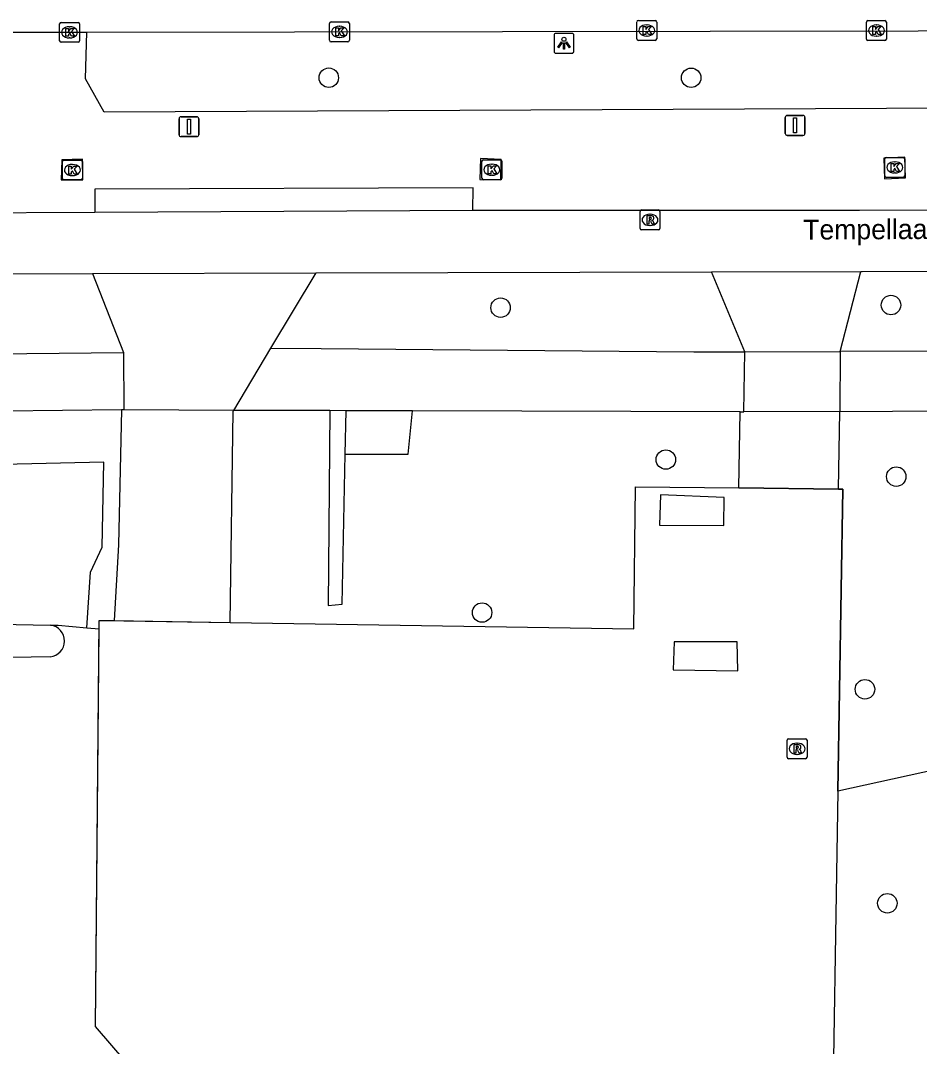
# Model space of a CAD drawing. Extents: x 160732 to 162105, y 387428 to 388479.
# Drawn here: x 160824.1 to 160869.3, y 388288.5 to 388340 of the extents above; entities that cross this region are included whole.
import ezdxf

# ---------------------------------------------------------------- set-up
doc = ezdxf.new("R2010")
doc.units = 0
for name, color, linetype in [('IMGEO_Berm_groen', 7, 'Continuous'), ('IMGEO_Boom', 7, 'Continuous'), ('IMGEO_Erf', 7, 'Continuous'), ('IMGEO_Fietspad_open', 7, 'Continuous'), ('IMGEO_Groenvoorziening', 7, 'Continuous'), ('IMGEO_Haag', 7, 'Continuous'), ('IMGEO_Hek', 7, 'Continuous'), ('IMGEO_Kolk', 7, 'Continuous'), ('IMGEO_Lichtpunt', 7, 'Continuous'), ('IMGEO_Openbare_ruimte_label', 7, 'Continuous'), ('IMGEO_Rijbaan_regionaal_gesloten', 7, 'Continuous'), ('IMGEO_Rioolput', 7, 'Continuous'), ('IMGEO_Verkeersbordpaal', 7, 'Continuous'), ('IMGEO_Voetpad_open', 7, 'Continuous'), ('IMGEO_Waterloop', 7, 'Continuous')]:
    doc.layers.add(name, color=color, linetype=linetype)

msp = doc.modelspace()

# ---------------------------------------------------------------- linework, layer by layer
at = {"layer": 'IMGEO_Berm_groen'}
msp.add_lwpolyline([(160958.33, 388337.953), (160955.414, 388335.943), (160949.557, 388333.455), (160946.326, 388335.988), (160828.33, 388335.445), (160827.393, 388337.122), (160827.446, 388339.467)], dxfattribs=at)
at = {"layer": 'IMGEO_Boom'}
for centre in [(160839.616, 388337.172), (160857.832, 388337.169), (160848.252, 388325.616), (160867.878, 388325.748), (160856.559, 388317.983), (160868.142, 388317.126), (160847.322, 388310.294), (160866.569, 388306.438), (160867.695, 388295.684)]:
    msp.add_circle(centre, 0.489, dxfattribs=at)
at = {"layer": 'IMGEO_Erf'}
for points in [[(160859.494, 388316.08), (160856.289, 388316.209), (160856.249, 388314.688), (160859.467, 388314.668), (160859.494, 388316.08)], [(160860.143, 388308.828), (160856.98, 388308.831), (160856.933, 388307.416), (160860.179, 388307.37), (160860.143, 388308.828)]]:
    msp.add_lwpolyline(points, dxfattribs=at)
at = {"layer": 'IMGEO_Fietspad_open'}
for points in [[(160846.854, 388330.5), (160846.875, 388331.641), (160827.861, 388331.568), (160827.854, 388330.405)], [(160846.854, 388330.5), (160827.854, 388330.405)], [(160948.514, 388330.666), (160948.148, 388330.665), (160866.301, 388330.493), (160846.854, 388330.5)], [(160827.854, 388330.405), (160814.057, 388330.327)], [(160755.948, 388328.392), (160760.439, 388328.038), (160771.107, 388327.578), (160775.664, 388327.463), (160782.867, 388327.387), (160794.417, 388327.291), (160806.927, 388327.23), (160817.787, 388327.309), (160827.738, 388327.334)], [(160827.738, 388327.334), (160838.976, 388327.375)], [(160838.976, 388327.375), (160858.861, 388327.415)], [(160858.861, 388327.415), (160866.359, 388327.435)], [(160866.359, 388327.435), (160866.422, 388327.435), (160948.07, 388327.597), (160952.894, 388327.601)]]:
    msp.add_lwpolyline(points, dxfattribs=at)
at = {"layer": 'IMGEO_Groenvoorziening'}
for points in [[(160839.672, 388320.441), (160839.58, 388310.643), (160840.283, 388310.715), (160840.437, 388318.25)], [(160840.437, 388318.25), (160840.482, 388320.438)], [(160840.437, 388318.25), (160843.608, 388318.256), (160843.817, 388320.428)], [(160834.65, 388309.796), (160854.955, 388309.47), (160855.041, 388316.62), (160860.223, 388316.558)], [(160865.213, 388301.314), (160865.461, 388316.495), (160865.235, 388316.498)], [(160825.631, 388309.669), (160826.011, 388309.655), (160827.456, 388309.525)], [(160865.213, 388301.314), (160864.893, 388281.692), (160834.148, 388282.21), (160827.887, 388289.487), (160828.067, 388309.47)], [(160871.548, 388302.717), (160865.213, 388301.314)]]:
    msp.add_lwpolyline(points, dxfattribs=at)
at = {"layer": 'IMGEO_Haag'}
for points in [[(160827.456, 388309.525), (160827.639, 388312.329), (160828.227, 388313.573), (160828.312, 388317.851), (160823.228, 388317.733)], [(160828.067, 388309.47), (160828.071, 388309.901), (160828.222, 388309.899), (160828.821, 388309.889)], [(160827.456, 388309.525), (160828.067, 388309.47)]]:
    msp.add_lwpolyline(points, dxfattribs=at)
at = {"layer": 'IMGEO_Hek'}
for points in [[(160834.65, 388309.796), (160854.955, 388309.47), (160855.041, 388316.62), (160860.223, 388316.558)], [(160860.223, 388316.558), (160865.235, 388316.498)], [(160865.235, 388316.498), (160865.461, 388316.495), (160865.213, 388301.314)], [(160865.213, 388301.314), (160864.893, 388281.692), (160834.148, 388282.21), (160827.887, 388289.487), (160828.071, 388309.901)], [(160828.071, 388309.901), (160828.235, 388309.896)], [(160828.235, 388309.896), (160834.65, 388309.796)]]:
    msp.add_lwpolyline(points, dxfattribs=at)
at = {"layer": 'IMGEO_Kolk'}
for p, q in [((160826.082, 388339.026), (160826.082, 388339.878)), ((160826.157, 388339.952), (160827.009, 388339.952)), ((160826.57, 388339.732), (160826.595, 388339.732)), ((160827.083, 388339.878), (160827.083, 388339.026)), ((160839.652, 388339.051), (160839.652, 388339.903)), ((160839.727, 388339.977), (160840.579, 388339.977)), ((160840.14, 388339.757), (160840.165, 388339.757)), ((160840.653, 388339.903), (160840.653, 388339.051)), ((160855.102, 388339.12), (160855.102, 388339.972)), ((160855.177, 388340.046), (160856.029, 388340.046)), ((160855.59, 388339.826), (160855.615, 388339.826)), ((160856.103, 388339.972), (160856.103, 388339.12)), ((160866.647, 388339.116), (160866.647, 388339.968)), ((160866.722, 388340.042), (160867.574, 388340.042)), ((160867.135, 388339.822), (160867.16, 388339.822)), ((160867.648, 388339.968), (160867.648, 388339.116)), ((160840.163, 388339.197), (160840.138, 388339.197)), ((160855.613, 388339.266), (160855.588, 388339.266)), ((160867.158, 388339.262), (160867.133, 388339.262)), ((160827.009, 388338.952), (160826.157, 388338.952)), ((160826.593, 388339.172), (160826.568, 388339.172)), ((160840.579, 388338.977), (160839.727, 388338.977)), ((160856.029, 388339.046), (160855.177, 388339.046)), ((160867.574, 388339.042), (160866.722, 388339.042)), ((160826.3, 388333.033), (160827.152, 388333.033)), ((160847.389, 388333.048), (160848.241, 388333.048)), ((160867.569, 388332.239), (160867.569, 388333.091)), ((160867.644, 388333.165), (160868.496, 388333.165)), ((160868.57, 388333.091), (160868.57, 388332.239)), ((160826.225, 388332.107), (160826.225, 388332.959)), ((160826.713, 388332.813), (160826.738, 388332.813)), ((160827.226, 388332.959), (160827.226, 388332.107)), ((160847.314, 388332.122), (160847.314, 388332.974)), ((160847.802, 388332.828), (160847.827, 388332.828)), ((160848.315, 388332.974), (160848.315, 388332.122)), ((160868.057, 388332.945), (160868.082, 388332.945)), ((160827.152, 388332.033), (160826.3, 388332.033)), ((160826.736, 388332.253), (160826.711, 388332.253)), ((160848.241, 388332.048), (160847.389, 388332.048)), ((160847.825, 388332.268), (160847.8, 388332.268)), ((160868.496, 388332.165), (160867.644, 388332.165)), ((160868.08, 388332.385), (160868.055, 388332.385))]:
    msp.add_line(p, q, dxfattribs=at)
for points in [[(160826.082, 388339.026), (160826.082, 388339.878)], [(160826.157, 388339.952), (160827.009, 388339.952)], [(160827.083, 388339.878), (160827.083, 388339.026)], [(160839.652, 388339.051), (160839.652, 388339.903)], [(160839.727, 388339.977), (160840.579, 388339.977)], [(160840.653, 388339.903), (160840.653, 388339.051)], [(160855.102, 388339.12), (160855.102, 388339.972)], [(160855.177, 388340.046), (160856.029, 388340.046)], [(160855.423, 388339.746), (160855.546, 388339.746), (160855.546, 388339.595), (160855.676, 388339.746), (160855.84, 388339.746), (160855.694, 388339.595), (160855.847, 388339.346), (160855.695, 388339.346), (160855.61, 388339.51), (160855.546, 388339.443), (160855.546, 388339.346), (160855.423, 388339.346), (160855.423, 388339.746)], [(160856.103, 388339.972), (160856.103, 388339.12)], [(160866.647, 388339.116), (160866.647, 388339.968)], [(160866.722, 388340.042), (160867.574, 388340.042)], [(160866.968, 388339.742), (160867.091, 388339.742), (160867.091, 388339.591), (160867.221, 388339.742), (160867.385, 388339.742), (160867.239, 388339.591), (160867.392, 388339.342), (160867.24, 388339.342), (160867.155, 388339.506), (160867.091, 388339.439), (160867.091, 388339.342), (160866.968, 388339.342), (160866.968, 388339.742)], [(160867.648, 388339.968), (160867.648, 388339.116)], [(160826.403, 388339.652), (160826.526, 388339.652), (160826.526, 388339.501), (160826.656, 388339.652), (160826.82, 388339.652), (160826.674, 388339.501), (160826.827, 388339.252), (160826.675, 388339.252), (160826.59, 388339.416), (160826.526, 388339.349), (160826.526, 388339.252), (160826.403, 388339.252), (160826.403, 388339.652)], [(160839.973, 388339.677), (160840.096, 388339.677), (160840.096, 388339.526), (160840.226, 388339.677), (160840.39, 388339.677), (160840.244, 388339.526), (160840.397, 388339.277), (160840.245, 388339.277), (160840.16, 388339.441), (160840.096, 388339.374), (160840.096, 388339.277), (160839.973, 388339.277), (160839.973, 388339.677)], [(160827.009, 388338.952), (160826.157, 388338.952)], [(160840.579, 388338.977), (160839.727, 388338.977)], [(160856.029, 388339.046), (160855.177, 388339.046)], [(160867.574, 388339.042), (160866.722, 388339.042)], [(160826.3, 388333.033), (160827.152, 388333.033)], [(160847.389, 388333.048), (160848.241, 388333.048)], [(160867.569, 388332.239), (160867.569, 388333.091)], [(160867.644, 388333.165), (160868.496, 388333.165)], [(160868.57, 388333.091), (160868.57, 388332.239)], [(160826.225, 388332.107), (160826.225, 388332.959)], [(160826.546, 388332.733), (160826.669, 388332.733), (160826.669, 388332.582), (160826.799, 388332.733), (160826.963, 388332.733), (160826.817, 388332.582), (160826.97, 388332.333), (160826.818, 388332.333), (160826.733, 388332.497), (160826.669, 388332.43), (160826.669, 388332.333), (160826.546, 388332.333), (160826.546, 388332.733)], [(160827.226, 388332.959), (160827.226, 388332.107)], [(160847.314, 388332.122), (160847.314, 388332.974)], [(160847.635, 388332.748), (160847.758, 388332.748), (160847.758, 388332.597), (160847.888, 388332.748), (160848.052, 388332.748), (160847.906, 388332.597), (160848.059, 388332.348), (160847.907, 388332.348), (160847.822, 388332.512), (160847.758, 388332.445), (160847.758, 388332.348), (160847.635, 388332.348), (160847.635, 388332.748)], [(160848.315, 388332.974), (160848.315, 388332.122)], [(160867.89, 388332.865), (160868.013, 388332.865), (160868.013, 388332.714), (160868.143, 388332.865), (160868.307, 388332.865), (160868.161, 388332.714), (160868.314, 388332.465), (160868.162, 388332.465), (160868.077, 388332.629), (160868.013, 388332.562), (160868.013, 388332.465), (160867.89, 388332.465), (160867.89, 388332.865)], [(160827.152, 388332.033), (160826.3, 388332.033)], [(160848.241, 388332.048), (160847.389, 388332.048)], [(160868.496, 388332.165), (160867.644, 388332.165)]]:
    msp.add_lwpolyline(points, dxfattribs=at)
for centre, start, end in [((160826.159, 388339.876), 91.552, 178.448), ((160826.159, 388339.876), 91.552, 178.448), ((160827.007, 388339.876), 1.552, 88.448), ((160827.007, 388339.876), 1.552, 88.448), ((160839.729, 388339.901), 91.552, 178.448), ((160839.729, 388339.901), 91.552, 178.448), ((160840.577, 388339.901), 1.552, 88.448), ((160840.577, 388339.901), 1.552, 88.448), ((160855.179, 388339.97), 91.552, 178.448), ((160855.179, 388339.97), 91.552, 178.448), ((160856.027, 388339.97), 1.552, 88.448), ((160856.027, 388339.97), 1.552, 88.448), ((160866.724, 388339.966), 91.552, 178.448), ((160866.724, 388339.966), 91.552, 178.448), ((160867.572, 388339.966), 1.552, 88.448), ((160867.572, 388339.966), 1.552, 88.448), ((160826.159, 388339.028), 181.552, 268.448), ((160826.159, 388339.028), 181.552, 268.448), ((160827.007, 388339.028), 271.552, 358.448), ((160827.007, 388339.028), 271.552, 358.448), ((160839.729, 388339.053), 181.552, 268.448), ((160839.729, 388339.053), 181.552, 268.448), ((160840.577, 388339.053), 271.552, 358.448), ((160840.577, 388339.053), 271.552, 358.448), ((160855.179, 388339.122), 181.552, 268.448), ((160855.179, 388339.122), 181.552, 268.448), ((160856.027, 388339.122), 271.552, 358.448), ((160856.027, 388339.122), 271.552, 358.448), ((160866.724, 388339.118), 181.552, 268.448), ((160866.724, 388339.118), 181.552, 268.448), ((160867.572, 388339.118), 271.552, 358.448), ((160867.572, 388339.118), 271.552, 358.448), ((160826.302, 388332.957), 91.552, 178.448), ((160826.302, 388332.957), 91.552, 178.448), ((160827.15, 388332.957), 1.552, 88.448), ((160827.15, 388332.957), 1.552, 88.448), ((160847.391, 388332.972), 91.552, 178.448), ((160847.391, 388332.972), 91.552, 178.448), ((160848.239, 388332.972), 1.552, 88.448), ((160848.239, 388332.972), 1.552, 88.448), ((160867.646, 388333.089), 91.552, 178.448), ((160867.646, 388333.089), 91.552, 178.448), ((160868.494, 388333.089), 1.552, 88.448), ((160868.494, 388333.089), 1.552, 88.448), ((160826.302, 388332.109), 181.552, 268.448), ((160826.302, 388332.109), 181.552, 268.448), ((160827.15, 388332.109), 271.552, 358.448), ((160827.15, 388332.109), 271.552, 358.448), ((160847.391, 388332.124), 181.552, 268.448), ((160847.391, 388332.124), 181.552, 268.448), ((160848.239, 388332.124), 271.552, 358.448), ((160848.239, 388332.124), 271.552, 358.448), ((160867.646, 388332.241), 181.552, 268.448), ((160867.646, 388332.241), 181.552, 268.448), ((160868.494, 388332.241), 271.552, 358.448), ((160868.494, 388332.241), 271.552, 358.448)]:
    msp.add_arc(centre, 0.0765, start, end, dxfattribs=at)
for centre, major_axis, ratio, start_param, end_param in [((160826.569, 388339.452), (-0.387, 0.002), 0.722429, 4.712389, 7.853982), ((160826.594, 388339.452), (-0.39, 0.002), 0.717154, 1.570796, 4.712389), ((160840.139, 388339.477), (-0.387, 0.002), 0.722429, 4.712389, 7.853982), ((160840.164, 388339.477), (-0.39, 0.002), 0.717154, 1.570796, 4.712389), ((160855.589, 388339.546), (-0.387, 0.002), 0.722429, 4.712389, 7.853982), ((160855.614, 388339.546), (-0.39, 0.002), 0.717154, 1.570796, 4.712389), ((160867.134, 388339.542), (-0.387, 0.002), 0.722429, 4.712389, 7.853982), ((160867.159, 388339.542), (-0.39, 0.002), 0.717154, 1.570796, 4.712389), ((160826.712, 388332.533), (-0.387, 0.002), 0.722429, 4.712389, 7.853982), ((160826.737, 388332.533), (-0.39, 0.002), 0.717154, 1.570796, 4.712389), ((160847.801, 388332.548), (-0.387, 0.002), 0.722429, 4.712389, 7.853982), ((160847.826, 388332.548), (-0.39, 0.002), 0.717154, 1.570796, 4.712389), ((160868.056, 388332.665), (-0.387, 0.002), 0.722429, 4.712389, 7.853982), ((160868.081, 388332.665), (-0.39, 0.002), 0.717154, 1.570796, 4.712389)]:
    msp.add_ellipse(centre, major_axis=major_axis, ratio=ratio, start_param=start_param, end_param=end_param, dxfattribs=at)
at = {"layer": 'IMGEO_Lichtpunt'}
for p, q in [((160850.939, 388339.306), (160850.939, 388338.499)), ((160850.939, 388339.306), (160850.939, 388338.499)), ((160851.841, 388339.401), (160851.033, 388339.401)), ((160851.841, 388339.401), (160851.033, 388339.401)), ((160851.935, 388338.499), (160851.935, 388339.306)), ((160851.935, 388338.499), (160851.935, 388339.306)), ((160851.033, 388338.405), (160851.841, 388338.405)), ((160851.033, 388338.405), (160851.841, 388338.405))]:
    msp.add_line(p, q, dxfattribs=at)
for points in [[(160851.313, 388338.97), (160851.352, 388338.942), (160851.164, 388338.68), (160851.126, 388338.707), (160851.313, 388338.97)], [(160851.415, 388338.922), (160851.462, 388338.922), (160851.462, 388338.6), (160851.415, 388338.6), (160851.415, 388338.922)], [(160851.525, 388338.942), (160851.563, 388338.969), (160851.75, 388338.707), (160851.711, 388338.679), (160851.525, 388338.942)]]:
    msp.add_lwpolyline(points, dxfattribs=at)
msp.add_circle((160851.438, 388339.104), 0.0994, dxfattribs=at)
for centre, start, end in [((160851.033, 388339.306), 90, 180), ((160851.033, 388339.306), 90, 180), ((160851.841, 388339.306), 0, 90), ((160851.841, 388339.306), 0, 90), ((160851.033, 388338.499), 180, 270), ((160851.033, 388338.499), 180, 270), ((160851.841, 388338.499), 270, 0), ((160851.841, 388338.499), 270, 360)]:
    msp.add_arc(centre, 0.0946, start, end, dxfattribs=at)
at = {"layer": 'IMGEO_Rijbaan_regionaal_gesloten'}
for points in [[(160823.488, 388339.461), (160827.446, 388339.467)], [(160827.446, 388339.467), (160952.808, 388339.661), (160958.509, 388339.67)]]:
    msp.add_lwpolyline(points, dxfattribs=at)
at = {"layer": 'IMGEO_Rioolput'}
for p, q in [((160855.261, 388329.602), (160855.261, 388330.454)), ((160855.336, 388330.528), (160856.188, 388330.528)), ((160856.262, 388330.454), (160856.262, 388329.602)), ((160855.749, 388330.308), (160855.774, 388330.308)), ((160856.188, 388329.528), (160855.336, 388329.528)), ((160855.772, 388329.748), (160855.747, 388329.748)), ((160862.657, 388303.023), (160862.657, 388303.875)), ((160862.732, 388303.949), (160863.584, 388303.949)), ((160863.145, 388303.729), (160863.17, 388303.729)), ((160863.658, 388303.875), (160863.658, 388303.023)), ((160863.168, 388303.169), (160863.143, 388303.169)), ((160863.584, 388302.949), (160862.732, 388302.949))]:
    msp.add_line(p, q, dxfattribs=at)
for points in [[(160855.261, 388329.602), (160855.261, 388330.454)], [(160855.336, 388330.528), (160856.188, 388330.528)], [(160856.262, 388330.454), (160856.262, 388329.602)], [(160855.85, 388330.226), (160855.598, 388330.228), (160855.598, 388329.828)], [(160855.598, 388329.828), (160855.722, 388329.828), (160855.722, 388329.99), (160855.733, 388329.99)], [(160855.776, 388330.147), (160855.722, 388330.147), (160855.722, 388330.066)], [(160855.722, 388330.066), (160855.774, 388330.066)], [(160855.78, 388329.961), (160855.851, 388329.828), (160855.991, 388329.828), (160855.926, 388329.954)], [(160856.188, 388329.528), (160855.336, 388329.528)], [(160862.657, 388303.023), (160862.657, 388303.875)], [(160862.732, 388303.949), (160863.584, 388303.949)], [(160863.246, 388303.647), (160862.994, 388303.649), (160862.994, 388303.249)], [(160863.658, 388303.875), (160863.658, 388303.023)], [(160862.994, 388303.249), (160863.118, 388303.249), (160863.118, 388303.411), (160863.129, 388303.411)], [(160863.172, 388303.568), (160863.118, 388303.568), (160863.118, 388303.487)], [(160863.118, 388303.487), (160863.17, 388303.487)], [(160863.176, 388303.382), (160863.247, 388303.249), (160863.387, 388303.249), (160863.322, 388303.375)], [(160863.584, 388302.949), (160862.732, 388302.949)]]:
    msp.add_lwpolyline(points, dxfattribs=at)
for centre, radius, start, end in [((160855.338, 388330.452), 0.0765, 91.552, 178.448), ((160855.338, 388330.452), 0.0765, 91.552, 178.448), ((160856.186, 388330.452), 0.0765, 1.552, 88.448), ((160856.186, 388330.452), 0.0765, 1.552, 88.448), ((160855.732, 388329.937), 0.0533, 26.0293, 88.6989), ((160855.758, 388330.255), 0.19, 274.7715, 282.9687), ((160855.782, 388330.051), 0.0964, 77.0061, 93.1865), ((160855.796, 388330.108), 0.0378, 276.6634, 79.6772), ((160855.849, 388330.116), 0.109, 350.3612, 89.416), ((160855.847, 388330.116), 0.112, 277.5842, 350.9817), ((160855.831, 388329.901), 0.108, 29.5134, 73.7905), ((160855.338, 388329.604), 0.0765, 181.552, 268.448), ((160855.338, 388329.604), 0.0765, 181.552, 268.448), ((160856.186, 388329.604), 0.0765, 271.552, 358.448), ((160856.186, 388329.604), 0.0765, 271.552, 358.448), ((160862.734, 388303.873), 0.0765, 91.552, 178.448), ((160862.734, 388303.873), 0.0765, 91.552, 178.448), ((160863.245, 388303.537), 0.109, 350.3612, 89.416), ((160863.582, 388303.873), 0.0765, 1.552, 88.448), ((160863.582, 388303.873), 0.0765, 1.552, 88.448), ((160863.128, 388303.358), 0.0533, 26.0293, 88.6989), ((160863.154, 388303.676), 0.19, 274.7715, 282.9687), ((160863.178, 388303.472), 0.0964, 77.0061, 93.1865), ((160863.192, 388303.529), 0.0378, 276.6634, 79.6772), ((160863.243, 388303.537), 0.112, 277.5842, 350.9817), ((160863.227, 388303.322), 0.108, 29.5134, 73.7905), ((160862.734, 388303.025), 0.0765, 181.552, 268.448), ((160862.734, 388303.025), 0.0765, 181.552, 268.448), ((160863.582, 388303.025), 0.0765, 271.552, 358.448), ((160863.582, 388303.025), 0.0765, 271.552, 358.448)]:
    msp.add_arc(centre, radius, start, end, dxfattribs=at)
for centre, major_axis, ratio, start_param, end_param in [((160855.748, 388330.028), (-0.387, 0.002), 0.722429, 4.712389, 7.853982), ((160855.773, 388330.028), (-0.39, 0.002), 0.717154, 1.570796, 4.712389), ((160863.144, 388303.449), (-0.387, 0.002), 0.722429, 4.712389, 7.853982), ((160863.169, 388303.449), (-0.39, 0.002), 0.717154, 1.570796, 4.712389)]:
    msp.add_ellipse(centre, major_axis=major_axis, ratio=ratio, start_param=start_param, end_param=end_param, dxfattribs=at)
at = {"layer": 'IMGEO_Verkeersbordpaal'}
for p, q in [((160832.089, 388334.31), (160832.089, 388335.11)), ((160832.089, 388335.11), (160832.089, 388334.31)), ((160832.189, 388335.21), (160832.979, 388335.21)), ((160832.979, 388335.21), (160832.189, 388335.21)), ((160833.079, 388335.11), (160833.079, 388334.31)), ((160833.079, 388334.31), (160833.079, 388335.11)), ((160862.563, 388334.376), (160862.563, 388335.176)), ((160862.563, 388335.176), (160862.563, 388334.376)), ((160862.663, 388335.276), (160863.453, 388335.276)), ((160863.453, 388335.276), (160862.663, 388335.276)), ((160863.553, 388335.176), (160863.553, 388334.376)), ((160863.553, 388334.376), (160863.553, 388335.176)), ((160832.979, 388334.21), (160832.189, 388334.21)), ((160832.189, 388334.21), (160832.979, 388334.21)), ((160863.453, 388334.276), (160862.663, 388334.276)), ((160862.663, 388334.276), (160863.453, 388334.276))]:
    msp.add_line(p, q, dxfattribs=at)
for points in [[(160832.509, 388335.085), (160832.659, 388335.085), (160832.659, 388334.335), (160832.509, 388334.335), (160832.509, 388335.085)], [(160862.983, 388335.151), (160863.133, 388335.151), (160863.133, 388334.401), (160862.983, 388334.401), (160862.983, 388335.151)]]:
    msp.add_lwpolyline(points, dxfattribs=at)
for centre, start, end in [((160832.189, 388335.11), 90, 180), ((160832.189, 388335.11), 90, 180), ((160832.979, 388335.11), 0, 90), ((160832.979, 388335.11), 360, 90), ((160862.663, 388335.176), 90, 180), ((160862.663, 388335.176), 90, 180), ((160863.453, 388335.176), 0, 90), ((160863.453, 388335.176), 360, 90), ((160832.189, 388334.31), 180, 270), ((160832.189, 388334.31), 180, 270), ((160832.979, 388334.31), 270, 0), ((160832.979, 388334.31), 270, 0), ((160862.663, 388334.376), 180, 270), ((160862.663, 388334.376), 180, 270), ((160863.453, 388334.376), 270, 0), ((160863.453, 388334.376), 270, 0)]:
    msp.add_arc(centre, 0.1, start, end, dxfattribs=at)
at = {"layer": 'IMGEO_Voetpad_open'}
for points in [[(160827.255, 388332.033), (160827.24, 388333.078), (160826.203, 388333.049), (160826.169, 388332.032), (160827.255, 388332.033)], [(160848.268, 388332.045), (160848.286, 388333.065), (160847.245, 388333.105), (160847.201, 388332.059), (160848.268, 388332.045)], [(160867.551, 388332.086), (160868.601, 388332.134), (160868.58, 388333.177), (160867.523, 388333.129), (160867.551, 388332.086)], [(160755.948, 388328.392), (160755.957, 388322.55), (160779.067, 388322.779), (160786.643, 388322.796), (160786.659, 388320.747), (160814.806, 388320.872), (160814.71, 388323.21), (160829.292, 388323.36)], [(160836.705, 388323.58), (160838.976, 388327.375)], [(160860.53, 388323.403), (160858.861, 388327.415)], [(160952.894, 388327.601), (160952.934, 388323.839), (160947.477, 388323.803), (160924.389, 388323.53), (160897.884, 388323.448), (160865.329, 388323.408)], [(160865.329, 388323.408), (160866.359, 388327.435)], [(160827.738, 388327.334), (160829.292, 388323.36)], [(160829.292, 388323.36), (160829.308, 388320.482)], [(160834.835, 388320.456), (160836.705, 388323.58)], [(160836.705, 388323.58), (160839.24, 388323.557), (160857.962, 388323.4), (160860.53, 388323.403)], [(160860.481, 388320.377), (160860.53, 388323.403)], [(160860.53, 388323.403), (160865.329, 388323.408)], [(160865.329, 388323.408), (160865.306, 388320.404)], [(160829.187, 388320.481), (160823.262, 388320.422), (160823.228, 388317.733)], [(160829.187, 388320.481), (160829.041, 388313.705), (160828.821, 388309.889)], [(160829.308, 388320.482), (160829.187, 388320.481)], [(160834.835, 388320.456), (160829.308, 388320.482)], [(160834.65, 388309.796), (160834.81, 388320.415), (160834.835, 388320.456)], [(160839.672, 388320.441), (160835.076, 388320.455), (160834.835, 388320.456)], [(160840.482, 388320.438), (160839.672, 388320.441)], [(160843.817, 388320.428), (160840.482, 388320.438)], [(160860.288, 388320.378), (160843.817, 388320.428)], [(160860.223, 388316.558), (160860.288, 388320.378)], [(160860.288, 388320.378), (160860.481, 388320.377)], [(160865.306, 388320.404), (160860.481, 388320.377)], [(160865.235, 388316.498), (160865.306, 388320.404)], [(160865.306, 388320.404), (160873.241, 388320.455)], [(160865.235, 388316.498), (160860.223, 388316.558)], [(160828.821, 388309.889), (160834.65, 388309.796)]]:
    msp.add_lwpolyline(points, dxfattribs=at)
at = {"layer": 'IMGEO_Waterloop'}
for points in [[(160805.746, 388310.04), (160825.631, 388309.669)], [(160825.605, 388308.073), (160805.436, 388307.718)]]:
    msp.add_lwpolyline(points, dxfattribs=at)
msp.add_arc((160825.528, 388308.872), 0.803, 275.5056, 82.6277, dxfattribs=at)

# ---------------------------------------------------------------- texts
at = {"layer": 'IMGEO_Openbare_ruimte_label'}
msp.add_text('Tempellaan', height=1, rotation=0.2865, dxfattribs=at).set_placement((160863.467, 388329.036))

doc.saveas('drawing.dxf')
